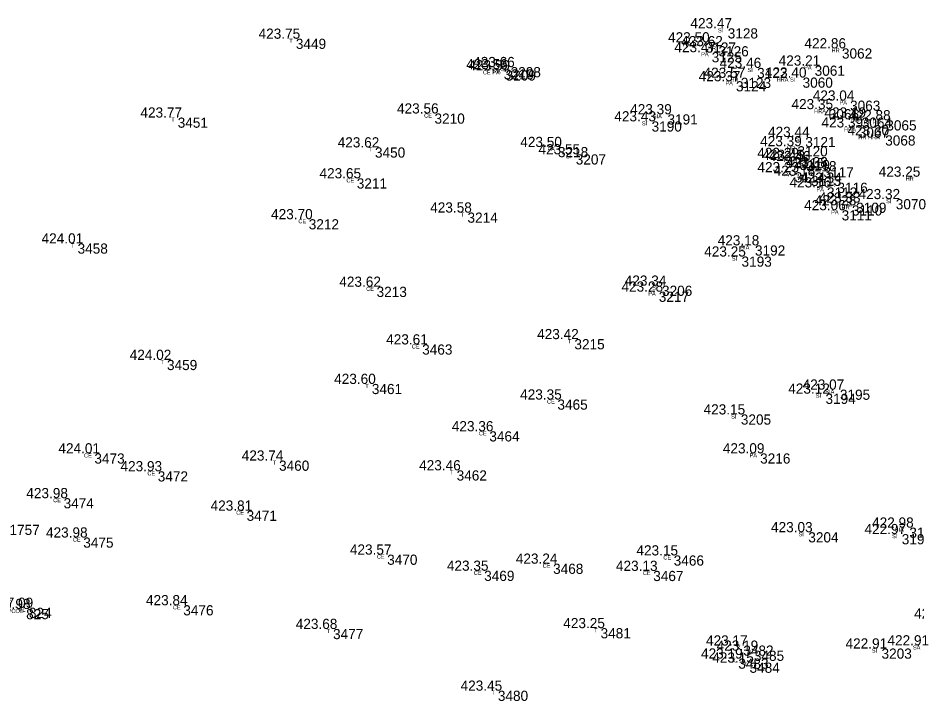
# Model space of a CAD drawing. Extents: x -639390 to -639075, y -1138747 to -1138358.
# Drawn here: x -639201.5 to -639135.3, y -1138619.1 to -1138568.7 of the extents above; entities that cross this region are included whole.
import ezdxf

# ---------------------------------------------------------------- set-up
doc = ezdxf.new("R2010")
doc.units = 0
for name, color, linetype in [('Vrstva 11', 7, 'Continuous'), ('Vrstva 12', 7, 'Continuous'), ('Vrstva 13', 7, 'Continuous'), ('Vrstva 57', 7, 'Continuous')]:
    doc.layers.add(name, color=color, linetype=linetype)

msp = doc.modelspace()

# ---------------------------------------------------------------- linework, layer by layer
at = {"layer": 'Vrstva 11'}
for p, q in [((-639149.45, -1138569.5), (-639149.45, -1138569.5)), ((-639181.28, -1138570.27), (-639181.28, -1138570.27)), ((-639151.07, -1138570.54), (-639151.07, -1138570.54)), ((-639150.13, -1138570.82), (-639150.13, -1138570.82)), ((-639150.63, -1138571.26), (-639150.63, -1138571.26)), ((-639141.03, -1138570.98), (-639141.03, -1138570.98)), ((-639165.96, -1138572.52), (-639165.96, -1138572.52)), ((-639165.82, -1138572.6), (-639165.82, -1138572.6)), ((-639165.45, -1138572.36), (-639165.45, -1138572.36)), ((-639147.28, -1138572.42), (-639147.28, -1138572.42)), ((-639143.04, -1138572.25), (-639143.04, -1138572.25)), ((-639148.84, -1138573.4), (-639148.84, -1138573.4)), ((-639148.48, -1138573.15), (-639148.48, -1138573.15)), ((-639143.93, -1138573.13), (-639143.93, -1138573.13)), ((-639140.43, -1138574.83), (-639140.43, -1138574.83)), ((-639142, -1138575.46), (-639142, -1138575.46)), ((-639189.99, -1138576.08), (-639189.99, -1138576.08)), ((-639171.06, -1138575.78), (-639171.06, -1138575.78)), ((-639153.89, -1138575.84), (-639153.89, -1138575.84)), ((-639139.57, -1138576.08), (-639139.57, -1138576.08)), ((-639155.06, -1138576.36), (-639155.06, -1138576.36)), ((-639139.79, -1138576.81), (-639139.79, -1138576.81)), ((-639137.76, -1138576.28), (-639137.76, -1138576.28)), ((-639137.84, -1138577.39), (-639137.84, -1138577.39)), ((-639143.73, -1138577.51), (-639143.73, -1138577.51)), ((-639175.45, -1138578.28), (-639175.45, -1138578.28)), ((-639161.96, -1138578.25), (-639161.96, -1138578.25)), ((-639160.65, -1138578.79), (-639160.65, -1138578.79)), ((-639144.31, -1138578.19), (-639144.31, -1138578.19)), ((-639144.52, -1138579.06), (-639144.52, -1138579.06)), ((-639144.15, -1138579.2), (-639144.15, -1138579.2)), ((-639143.66, -1138579.29), (-639143.66, -1138579.29)), ((-639144.51, -1138580.11), (-639144.51, -1138580.11)), ((-639142.39, -1138579.74), (-639142.39, -1138579.74)), ((-639176.79, -1138580.56), (-639176.79, -1138580.56)), ((-639143.31, -1138580.37), (-639143.31, -1138580.37)), ((-639135.57, -1138580.44), (-639135.57, -1138580.44)), ((-639142.13, -1138581.23), (-639142.13, -1138581.23)), ((-639141.36, -1138580.88), (-639141.36, -1138580.88)), ((-639137.06, -1138582.09), (-639137.06, -1138582.09)), ((-639140.29, -1138582.55), (-639140.29, -1138582.55)), ((-639139.98, -1138582.35), (-639139.98, -1138582.35)), ((-639168.63, -1138583.08), (-639168.63, -1138583.08)), ((-639141.05, -1138582.91), (-639141.05, -1138582.91)), ((-639180.33, -1138583.57), (-639180.33, -1138583.57)), ((-639197.37, -1138585.36), (-639197.37, -1138585.36)), ((-639147.44, -1138585.5), (-639147.44, -1138585.5)), ((-639148.43, -1138586.32), (-639148.43, -1138586.32)), ((-639175.33, -1138588.55), (-639175.33, -1138588.55)), ((-639154.29, -1138588.47), (-639154.29, -1138588.47)), ((-639154.53, -1138588.91), (-639154.53, -1138588.91)), ((-639160.75, -1138592.41), (-639160.75, -1138592.41)), ((-639171.97, -1138592.8), (-639171.97, -1138592.8)), ((-639190.78, -1138593.94), (-639190.78, -1138593.94)), ((-639175.68, -1138595.71), (-639175.68, -1138595.71)), ((-639142.24, -1138596.43), (-639142.24, -1138596.43)), ((-639141.18, -1138596.13), (-639141.18, -1138596.13)), ((-639162, -1138596.86), (-639162, -1138596.86)), ((-639148.48, -1138597.96), (-639148.48, -1138597.96)), ((-639167.02, -1138599.2), (-639167.02, -1138599.2)), ((-639196.13, -1138600.83), (-639196.13, -1138600.83)), ((-639147.06, -1138600.83), (-639147.06, -1138600.83)), ((-639182.52, -1138601.36), (-639182.52, -1138601.36)), ((-639191.46, -1138602.15), (-639191.46, -1138602.15)), ((-639169.43, -1138602.08), (-639169.43, -1138602.08)), ((-639198.4, -1138604.13), (-639198.4, -1138604.13)), ((-639184.91, -1138605.05), (-639184.91, -1138605.05)), ((-639136.06, -1138606.3), (-639136.06, -1138606.3)), ((-639196.95, -1138607.03), (-639196.95, -1138607.03)), ((-639143.51, -1138606.64), (-639143.51, -1138606.64)), ((-639136.62, -1138606.78), (-639136.62, -1138606.78)), ((-639174.55, -1138608.29), (-639174.55, -1138608.29)), ((-639153.43, -1138608.35), (-639153.43, -1138608.35)), ((-639162.32, -1138608.96), (-639162.32, -1138608.96)), ((-639167.4, -1138609.48), (-639167.4, -1138609.48)), ((-639154.94, -1138609.49), (-639154.94, -1138609.49)), ((-639201.16, -1138612.3), (-639201.16, -1138612.3)), ((-639200.96, -1138612.21), (-639200.96, -1138612.21)), ((-639189.58, -1138612.02), (-639189.58, -1138612.02)), ((-639178.54, -1138613.77), (-639178.54, -1138613.77)), ((-639158.82, -1138613.71), (-639158.82, -1138613.71)), ((-639148.3, -1138614.99), (-639148.3, -1138614.99)), ((-639138.11, -1138615.21), (-639138.11, -1138615.21)), ((-639147.52, -1138615.37), (-639147.52, -1138615.37)), ((-639148.67, -1138615.95), (-639148.67, -1138615.95)), ((-639147.84, -1138616.25), (-639147.84, -1138616.25)), ((-639166.39, -1138618.32), (-639166.39, -1138618.32))]:
    msp.add_line(p, q, dxfattribs=at)

# ---------------------------------------------------------------- texts
at = {"layer": 'Vrstva 12'}
for s, p in [('423.47 ', (-639151.919, -1138569.5)), ('423.75 ', (-639183.75, -1138570.27)), ('423.50 ', (-639153.569, -1138570.54)), ('423.62 ', (-639152.599, -1138570.82)), ('423.47 ', (-639153.099, -1138571.26)), ('422.86 ', (-639143.516, -1138570.98)), ('423.21 ', (-639145.415, -1138572.25)), ('423.56 ', (-639168.446, -1138572.52)), ('423.59 ', (-639168.289, -1138572.6)), ('423.66 ', (-639167.936, -1138572.36)), ('423.46 ', (-639149.766, -1138572.42)), ('423.37 ', (-639151.309, -1138573.4)), ('423.57 ', (-639150.949, -1138573.15)), ('423.40 ', (-639146.429, -1138573.13)), ('423.04 ', (-639142.899, -1138574.83)), ('423.35 ', (-639144.47, -1138575.46)), ('423.77 ', (-639192.459, -1138576.08)), ('423.56 ', (-639173.546, -1138575.78)), ('423.39 ', (-639156.359, -1138575.84)), ('423.19 ', (-639142.039, -1138576.08)), ('423.43 ', (-639157.529, -1138576.36)), ('423.39 ', (-639142.259, -1138576.81)), ('422.88 ', (-639140.229, -1138576.28)), ('423.44 ', (-639146.199, -1138577.51)), ('423.30 ', (-639140.339, -1138577.39)), ('423.39 ', (-639146.779, -1138578.19)), ('423.62 ', (-639177.919, -1138578.28)), ('423.50 ', (-639164.459, -1138578.25)), ('423.55 ', (-639163.12, -1138578.79)), ('423.29 ', (-639146.989, -1138579.06)), ('423.45 ', (-639146.62, -1138579.2)), ('423.46 ', (-639146.146, -1138579.29)), ('423.23 ', (-639146.979, -1138580.11)), ('423.38 ', (-639144.859, -1138579.74)), ('423.65 ', (-639179.26, -1138580.56)), ('423.18 ', (-639145.779, -1138580.37)), ('423.34 ', (-639143.829, -1138580.88)), ('423.25 ', (-639138.04, -1138580.44)), ('423.16 ', (-639144.616, -1138581.23)), ('423.32 ', (-639139.529, -1138582.09)), ('423.28 ', (-639142.759, -1138582.55)), ('423.33 ', (-639142.449, -1138582.35)), ('423.58 ', (-639171.099, -1138583.08)), ('423.06 ', (-639143.536, -1138582.91)), ('423.70 ', (-639182.829, -1138583.57)), ('424.01 ', (-639199.745, -1138585.36)), ('423.18 ', (-639149.909, -1138585.5)), ('423.25 ', (-639150.9, -1138586.32)), ('423.62 ', (-639177.799, -1138588.55)), ('423.34 ', (-639156.759, -1138588.47)), ('423.28 ', (-639156.999, -1138588.91)), ('423.61 ', (-639174.345, -1138592.8)), ('423.42 ', (-639163.219, -1138592.41)), ('424.02 ', (-639193.249, -1138593.94)), ('423.60 ', (-639178.179, -1138595.71)), ('423.12 ', (-639144.709, -1138596.43)), ('423.07 ', (-639143.649, -1138596.13)), ('423.35 ', (-639164.47, -1138596.86)), ('423.15 ', (-639150.95, -1138597.96)), ('423.36 ', (-639169.506, -1138599.2)), ('424.01 ', (-639198.505, -1138600.83)), ('423.74 ', (-639184.989, -1138601.36)), ('423.09 ', (-639149.529, -1138600.83)), ('423.93 ', (-639193.929, -1138602.15)), ('423.46 ', (-639171.916, -1138602.08)), ('423.98 ', (-639200.869, -1138604.13)), ('423.81 ', (-639187.285, -1138605.05)), ('423.03 ', (-639145.979, -1138606.64)), ('422.98 ', (-639138.529, -1138606.3)), ('423.98 ', (-639199.419, -1138607.03)), ('422.97 ', (-639139.089, -1138606.78)), ('423.57 ', (-639177.019, -1138608.29)), ('423.15 ', (-639155.9, -1138608.35)), ('423.24 ', (-639164.789, -1138608.96)), ('423.35 ', (-639169.87, -1138609.48)), ('423.13 ', (-639157.409, -1138609.49)), ('426.98 ', (-639203.629, -1138612.3)), ('427.09 ', (-639203.429, -1138612.21)), ('423.84 ', (-639192.049, -1138612.02)), ('422.84 ', (-639135.429, -1138613.01)), ('423.68 ', (-639181.009, -1138613.77)), ('423.25 ', (-639161.29, -1138613.71)), ('423.17 ', (-639150.769, -1138614.99)), ('422.91 ', (-639140.485, -1138615.21)), ('422.91 ', (-639137.395, -1138614.98)), ('423.19 ', (-639151.139, -1138615.95)), ('423.19 ', (-639149.989, -1138615.37)), ('423.15 ', (-639150.31, -1138616.25)), ('423.45 ', (-639168.86, -1138618.32))]:
    msp.add_text(s, height=0.75, dxfattribs=at).set_placement(p)
at = {"layer": 'Vrstva 13'}
for s, p in [(' 3128', (-639149.45, -1138570.25)), (' 3449', (-639181.28, -1138571.02)), (' 3127', (-639151.07, -1138571.29)), (' 3126', (-639150.13, -1138571.57)), (' 3125', (-639150.63, -1138572.01)), (' 3062', (-639141.03, -1138571.73)), (' 3219', (-639165.96, -1138573.27)), (' 3209', (-639165.82, -1138573.35)), (' 3208', (-639165.45, -1138573.11)), (' 3122', (-639147.28, -1138573.17)), (' 3061', (-639143.04, -1138573)), (' 3124', (-639148.84, -1138574.15)), (' 3123', (-639148.48, -1138573.9)), (' 3060', (-639143.93, -1138573.88)), (' 3063', (-639140.43, -1138575.58)), (' 3066', (-639142, -1138576.21)), (' 3451', (-639189.99, -1138576.83)), (' 3210', (-639171.06, -1138576.53)), (' 3191', (-639153.89, -1138576.59)), (' 3064', (-639139.57, -1138576.83)), (' 3190', (-639155.06, -1138577.11)), (' 3067', (-639139.79, -1138577.56)), (' 3065', (-639137.76, -1138577.03)), (' 3068', (-639137.84, -1138578.14)), (' 3121', (-639143.73, -1138578.26)), (' 3450', (-639175.45, -1138579.03)), (' 3218', (-639161.96, -1138579)), (' 3207', (-639160.65, -1138579.54)), (' 3120', (-639144.31, -1138578.94)), (' 3115', (-639144.52, -1138579.81)), (' 3119', (-639144.15, -1138579.95)), (' 3118', (-639143.66, -1138580.04)), (' 3114', (-639144.51, -1138580.86)), (' 3117', (-639142.39, -1138580.49)), (' 3211', (-639176.79, -1138581.31)), (' 3113', (-639143.31, -1138581.12)), (' 3112', (-639142.13, -1138581.98)), (' 3116', (-639141.36, -1138581.63)), (' 3070', (-639137.06, -1138582.84)), (' 3110', (-639140.29, -1138583.3)), (' 3109', (-639139.98, -1138583.1)), (' 3214', (-639168.63, -1138583.83)), (' 3111', (-639141.05, -1138583.66)), (' 3212', (-639180.33, -1138584.32)), (' 3458', (-639197.37, -1138586.11)), (' 3192', (-639147.44, -1138586.25)), (' 3193', (-639148.43, -1138587.07)), (' 3213', (-639175.33, -1138589.3)), (' 3206', (-639154.29, -1138589.22)), (' 3217', (-639154.53, -1138589.66)), (' 3215', (-639160.75, -1138593.16)), (' 3463', (-639171.97, -1138593.55)), (' 3459', (-639190.78, -1138594.69)), (' 3461', (-639175.68, -1138596.46)), (' 3194', (-639142.24, -1138597.18)), (' 3195', (-639141.18, -1138596.88)), (' 3465', (-639162, -1138597.61)), (' 3205', (-639148.48, -1138598.71)), (' 3464', (-639167.02, -1138599.95)), (' 3473', (-639196.13, -1138601.58)), (' 3216', (-639147.06, -1138601.58)), (' 3460', (-639182.52, -1138602.11)), (' 3472', (-639191.46, -1138602.9)), (' 3462', (-639169.43, -1138602.83)), (' 3474', (-639198.4, -1138604.88)), (' 3471', (-639184.91, -1138605.8)), (' 1757', (-639202.39, -1138606.84)), (' 3196', (-639136.06, -1138607.05)), (' 3475', (-639196.95, -1138607.78)), (' 3204', (-639143.51, -1138607.39)), (' 3197', (-639136.62, -1138607.53)), (' 3470', (-639174.55, -1138609.04)), (' 3466', (-639153.43, -1138609.1)), (' 3468', (-639162.32, -1138609.71)), (' 3469', (-639167.4, -1138610.23)), (' 3467', (-639154.94, -1138610.24)), (' 825', (-639201.16, -1138613.05)), (' 824', (-639200.96, -1138612.96)), (' 3476', (-639189.58, -1138612.77)), (' 3477', (-639178.54, -1138614.52)), (' 3481', (-639158.82, -1138614.46)), (' 3482', (-639148.3, -1138615.74)), (' 3203', (-639138.11, -1138615.96)), (' 3485', (-639147.52, -1138616.12)), (' 3483', (-639148.67, -1138616.7)), (' 3484', (-639147.84, -1138617)), (' 3480', (-639166.39, -1138619.07))]:
    msp.add_text(s, height=0.75, dxfattribs=at).set_placement(p)
at = {"layer": 'Vrstva 57'}
for s, p in [('SI', (-639149.888, -1138569.8)), ('T', (-639181.48, -1138570.57)), ('HR PA', (-639152.47, -1138570.84)), ('HR', (-639150.619, -1138571.12)), ('PA', (-639151.13, -1138571.56)), ('HR', (-639141.519, -1138571.28)), ('CE PA', (-639167.22, -1138572.9)), ('PA', (-639166.46, -1138572.82)), ('SI', (-639165.888, -1138572.66)), ('SI', (-639147.718, -1138572.72)), ('PA', (-639143.54, -1138572.55)), ('PA', (-639149.34, -1138573.7)), ('HR', (-639148.969, -1138573.45)), ('HRA SI', (-639145.568, -1138573.43)), ('PA', (-639140.93, -1138575.13)), ('HRA', (-639142.8, -1138575.76)), ('T', (-639190.19, -1138576.38)), ('CE', (-639171.547, -1138576.08)), ('SIA', (-639154.69, -1138576.14)), ('PA', (-639140.07, -1138576.38)), ('SI', (-639155.498, -1138576.66)), ('HRA', (-639140.59, -1138577.11)), ('PA HR', (-639139.149, -1138576.58)), ('HR HRA', (-639139.54, -1138577.69)), ('SI', (-639144.168, -1138577.81)), ('T', (-639175.65, -1138578.58)), ('PA', (-639162.46, -1138578.55)), ('SI', (-639161.088, -1138579.09)), ('HR', (-639144.799, -1138578.49)), ('PA', (-639145.02, -1138579.36)), ('HR', (-639144.639, -1138579.5)), ('HR', (-639144.149, -1138579.59)), ('PA', (-639145.01, -1138580.41)), ('HR', (-639142.879, -1138580.04)), ('CE', (-639177.277, -1138580.86)), ('PA', (-639143.81, -1138580.67)), ('HR', (-639136.059, -1138580.74)), ('PA', (-639142.63, -1138581.53)), ('HR', (-639141.849, -1138581.18)), ('SI', (-639137.498, -1138582.39)), ('HR', (-639140.779, -1138582.85)), ('SI', (-639140.418, -1138582.65)), ('T', (-639168.83, -1138583.38)), ('PA', (-639141.55, -1138583.21)), ('CE', (-639180.818, -1138583.87)), ('T', (-639197.57, -1138585.66)), ('SIA', (-639148.24, -1138585.8)), ('SI', (-639148.868, -1138586.62)), ('CE', (-639175.818, -1138588.85)), ('SI', (-639154.728, -1138588.77)), ('PA', (-639155.03, -1138589.21)), ('T', (-639160.95, -1138592.71)), ('CE', (-639172.458, -1138593.1)), ('T', (-639190.98, -1138594.24)), ('T', (-639175.88, -1138596.01)), ('SI', (-639142.678, -1138596.73)), ('SIA', (-639141.98, -1138596.43)), ('CE', (-639162.488, -1138597.16)), ('SI', (-639148.918, -1138598.26)), ('CE', (-639167.508, -1138599.5)), ('CE', (-639196.618, -1138601.13)), ('PA', (-639147.56, -1138601.13)), ('T', (-639182.72, -1138601.66)), ('CE', (-639191.948, -1138602.45)), ('T', (-639169.63, -1138602.38)), ('CE', (-639198.888, -1138604.43)), ('CE', (-639185.397, -1138605.35)), ('SIA', (-639136.86, -1138606.6)), ('CE', (-639197.438, -1138607.33)), ('SI', (-639143.948, -1138606.94)), ('SI', (-639137.058, -1138607.08)), ('CE', (-639175.037, -1138608.59)), ('CE', (-639153.917, -1138608.65)), ('CE', (-639162.807, -1138609.26)), ('CE', (-639167.888, -1138609.78)), ('CE', (-639155.427, -1138609.79)), ('PODE', (-639202.248, -1138612.6)), ('PL', (-639201.435, -1138612.51)), ('CE', (-639190.068, -1138612.32)), ('T', (-639178.74, -1138614.07)), ('T', (-639159.02, -1138614.01)), ('K', (-639148.475, -1138615.29)), ('SI', (-639138.548, -1138615.51)), ('SA', (-639135.52, -1138615.28)), ('K', (-639147.695, -1138615.67)), ('K', (-639148.845, -1138616.25)), ('K', (-639148.015, -1138616.55)), ('T', (-639166.59, -1138618.62))]:
    msp.add_text(s, height=0.3, dxfattribs=at).set_placement(p)

doc.saveas('drawing.dxf')
